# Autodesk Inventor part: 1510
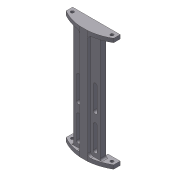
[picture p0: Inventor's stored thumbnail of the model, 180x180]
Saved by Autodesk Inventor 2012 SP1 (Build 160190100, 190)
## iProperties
Created: 2012-02
Part Number: 1510
Material: Aluminum-6061
Document SubType Name: Modeling
Designer: LACO
Density: 2.71 g/cm^3
Mass: 212.764 g
Surface Area: 319.605 cm^2
Volume: 78.5107 cm^3
Author: LACO
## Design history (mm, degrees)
sketch "Sketch1"
  geometry: L1 (0, 0)-(0, 116.84); L2 (-22.225, 116.84)-(22.225, 116.84); L3 (22.225, 116.84)-(22.225, 0); L4 (22.225, 0)-(-22.225, 0); L5 (-22.225, 0)-(-22.225, 116.84)
  constraints: 10 end point, 2 midpoint, 2 parallel, 1 horizontal, 1 perpendicular, 1 vertical, 1 other
  dimensions: "d0" = 116.84 distance of L2.end L3.end; "d1" = 44.45 distance of L2.start L2.end
extrude "Extrusion1" new body sketch "Sketch1" distance "d2" = 7.62; taper "d3" = 0 deg
sketch "Sketch2"
  geometry: L1 (-22.225, 116.84)-(-22.225, 0) reference; L2 (22.225, 0)-(22.225, 116.84) reference; L3 (-19.304, 116.84)-(-19.304, 0); L4 (-8.636, 116.84)-(-8.636, 0); L5 (8.636, 116.84)-(8.636, 0); L6 (19.304, 116.84)-(19.304, 0); L7 (0, 0)-(0, 116.84); L8 (-7.366, 116.84)-(-7.366, 0); L9 (7.366, 116.84)-(7.366, 0); 2 other entities
  constraints: 14 end point, 6 parallel, 18 other
  dimensions: "d6" = 8.636 distance between parallel lines of L4 L7; "d7" = 1.27 distance between parallel lines of L8 L4; "d10" = 19.304 distance between parallel lines of L7 L3
extrude "Extrusion2" join sketch "Sketch2" distance "d8" = 2.032; taper "d9" = 0 deg
sketch "Sketch3"
  geometry: L1 (0, 0)-(0, -9.652) reference; L2 (44.45, 0)-(44.45, -9.652) reference; L3 (44.45, 0)-(0, 0) reference; L4 (41.529, -7.62)-(2.921, -7.62) reference; L5 (-17.463, 0)-(61.913, 0); L6 (61.913, 0)-(61.912, -15.875); L7 (61.912, -15.875)-(-17.462, -15.875); L8 (-17.462, -15.875)-(-17.463, 0); L9 (-17.462, -15.875)-(-17.462, -5.018); L10 (61.912, -5.018)-(61.912, -15.875); L11 (41.529, -9.652)-(44.45, -9.652) reference; L12 (0, 0)-(0, 2.513); L13 (44.45, 0)-(44.45, 2.513); L14 (41.529, -7.62)-(2.921, -7.62) reference; L15 (41.529, -7.62)-(41.529, -9.652) reference; L16 (22.225, 0)-(22.225, -73.025); A1 r 78.74 centre (22.225, -73.025) between (0, 2.513) and (44.45, 2.513); A2 r 78.74 centre (22.225, -73.025) between (61.912, -5.018) and (-17.462, -5.018); 11 further points
  constraints: 18 end point, 6 point on circle, 6 point on line, 5 parallel, 2 centre point, 2 collinear, 2 midpoint, 2 perpendicular, 1 concentric, 1 horizontal
  dimensions: "d24" = 8.255 distance between parallel lines of L7 L4; "d26" = 17.4625 distance between parallel lines of L6 L2; "d32" = 157.48 diameter of A1; "d33" = 73.025 distance from line of L16.end L3
extrude "Extrusion3" join sketch "Sketch3" distance "d12" = 6.35; taper "d13" = 0 deg
sketch "Sketch4"
  geometry: L1 (-22.225, 116.84)-(22.225, 116.84) reference; L2 (22.225, 0)-(-22.225, 0) reference; L3 (-13.97, 116.84)-(-13.97, 0); L4 (0, 116.84)-(0, 0); L5 (-17.234, 104.775)-(-17.234, 66.675); L6 (-10.706, 104.775)-(-10.706, 66.675); L7 (-17.234, 47.625)-(-17.234, 9.525); L8 (-10.706, 47.625)-(-10.706, 9.525); L9 (22.225, 116.84)-(22.225, 0) reference; L10 (-22.225, 116.84)-(22.225, 116.84) reference; L11 (-22.225, 0)-(-22.225, 116.84) reference; L12 (22.225, 0)-(-22.225, 0) reference; A1 r 3.264 centre (-13.97, 104.775) between (-17.234, 104.775) and (-10.706, 104.775); A2 r 3.264 centre (-13.97, 66.675) between (-17.234, 66.675) and (-10.706, 66.675); A3 r 3.264 centre (-13.97, 47.625) between (-17.234, 47.625) and (-10.706, 47.625); A4 r 3.264 centre (-13.97, 9.525) between (-17.234, 9.525) and (-10.706, 9.525)
  constraints: 12 end point, 8 point on circle, 7 tangent, 6 point on line, 4 centre point, 3 equal radius, 2 parallel, 1 midpoint, 1 perpendicular
  dimensions: "d14" = 13.97 distance between parallel lines of L4 L3; "d15" = 6.5278 diameter of A2; "d16" = 38.1 distance of A2.centre A1.centre; "d18" = 38.1 distance of A4.centre A3.centre; "d19" = 19.05 distance of A3.centre A2.centre; "d29" = 9.525 distance from line of L2 A4.centre
extrude "Extrusion4" cut sketch "Sketch4" stored distance "d20" = 6.35; taper "d21" = 0 deg
mirror "Mirror1"
sketch "Sketch6"
  geometry: L1 (61.912, 15.875)-(-17.462, 15.875) reference; L2 (-17.462, 15.875)-(-17.462, 5.018) reference; L3 (61.912, 5.018)-(61.912, 15.875) reference; 3 further points
  dimensions: "d38" = 7.112 distance from line of L1 point (-10.858, 8.763); "d39" = 6.604 distance from line of point (-10.858, 8.763) L2; "d41" = 7.112 distance from line of L1 point (55.308, 8.763); "d49" = 6.604 distance from line of L3 point (55.308, 8.763)
hole "Hole1" sketch "Sketch6" at (-10.858, 8.763), (55.308, 8.763) diameter "d42" = 5.1054; stored, may be unused: countersink angle "d46" = 82 deg, drill point angle "d48" = 118 deg; dims "d43" = 19.05, "d44" = 9.779, "d45" = 6.35, "d47" = 25.4
workplane "Work Plane2"
mirror "Mirror2"
sketch "Sketch9"
  geometry: L1 (0, 0)-(44.45, 0) reference; L2 (44.45, 0)-(44.45, 9.652) reference; L3 (44.45, 9.652)-(0, 9.652) reference; L4 (41.529, 7.62)-(41.529, 9.652) reference; L5 (2.921, 9.652)-(0, 9.652) reference; L6 (2.921, 7.62)-(41.529, 7.62) reference; L7 (2.921, 7.62)-(2.921, 9.652) reference; L8 (0, 9.652)-(0, 0) reference
extrude "Extrusion8" join sketch "Sketch9" stored distance "d56" = 25.4; taper "d57" = 0 deg
sketch "Sketch7"
  geometry: L1 (44.45, 0)-(0, 0) reference; L2 (22.225, 7.62)-(22.225, -5.715); L3 (15.875, 0)-(15.875, -5.459); L4 (28.575, 0)-(28.575, -5.459); A1 r 78.74 centre (22.225, 73.025) between (-17.462, 5.018) and (61.912, 5.018) reference; A2 r 78.74 centre (22.225, 73.025) between (15.875, -5.459) and (28.575, -5.459)
  constraints: 6 end point, 5 point on circle, 2 parallel, 2 point on line, 1 centre point, 1 concentric, 1 other
  dimensions: "d50" = 12.7 distance between parallel lines of L4 L3
extrude "Extrusion6" join sketch "Sketch7" stored distance "d51" = 0; taper "d52" = 0 deg
sketch "Sketch11"
  geometry: L1 (61.912, 15.875)-(-17.462, 15.875) reference; L2 (2.921, 7.62)-(2.921, 9.652) reference; L3 (41.529, 7.62)-(2.921, 7.62) reference; L4 (41.529, 7.62)-(41.529, 9.652) reference; L5 (2.921, 9.652)-(2.921, 15.875); L6 (41.529, 9.652)-(41.529, 15.875); 1 further point
  constraints: 4 end point, 2 point on line, 1 parallel, 1 perpendicular
extrude "Extrusion10" cut sketch "Sketch11" stored distance "d62" = 25.4; taper "d63" = 0 deg
fillet "Fillet1" dims "d58" = 5.08, "d59" = 3.175
sketch "Sketch10"
  geometry: L1 (-6.35, -78.484)-(6.35, -78.484); L2 (6.35, -78.484)-(6.35, -78.74); L3 (6.35, -78.74)-(-6.35, -78.74); L4 (-6.35, -78.74)-(-6.35, -78.484); L5 (6.35, -78.484)-(6.35, -73.025) reference; L6 (6.35, -73.025)-(6.35, -78.484) reference; L7 (-6.35, -73.025)-(-6.35, -78.484) reference; L8 (-6.35, -78.484)-(-6.35, -73.025) reference; A1 r 78.74 centre (0, 0) between (-39.687, -68.007) and (39.687, -68.007) reference; 1 further point
  constraints: 8 end point, 2 parallel, 1 horizontal, 1 perpendicular, 1 tangent
extrude "Extrusion9" cut sketch "Sketch10" stored distance "d60" = 25.4; taper "d61" = 0 deg
body "Solid1"
node "Projected Loop1"
node "Projected Loop2"
node "Projected Loop3"
other parameters: "d55" = -94.615
